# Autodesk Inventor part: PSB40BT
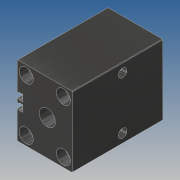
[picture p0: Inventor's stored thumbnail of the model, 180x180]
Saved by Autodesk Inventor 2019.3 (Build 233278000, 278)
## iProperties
Created: 2013-10
Part Number: PSB40BT
Material: Ogólny
Document SubType Name: Modeling
Designer: CADENGINEERING4
Density: 1 g/cm^3
Appearance: Ciemnoszara
Author: CADENGINEERING4
Revision Number: ÈÎºÎ
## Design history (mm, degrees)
feature "ÇÐ³ý-É¨Ãè3"
sketch "Szkic1"
  geometry: C1 r 4.25 at (45.5, -9) reference; C2 r 4.25 at (8.5, -9) reference; C3 r 4.25 at (8.5, -61) reference; C4 r 4.25 at (45.5, -61) reference; 1 further point
sketch "Szkic2"
  geometry: L1 (45.5, -13.25)-(54.5, -13.25) reference; L2 (2.903, -3.2)-(51.311, -3.2); L3 (51.311, -3.2)-(51.311, -13.25); L4 (51.311, -13.25)-(2.903, -13.25); L5 (2.903, -13.25)-(2.903, -3.2); L6 (-0.5, -56.75)-(8.5, -56.75) reference; L7 (2.903, -56.75)-(50.648, -56.75); L8 (50.648, -56.75)-(50.648, -68); L9 (50.648, -68)-(2.903, -68); L10 (2.903, -68)-(2.903, -56.75); 1 further point
  constraints: 16 end point, 4 parallel, 3 point on line, 2 horizontal, 2 perpendicular
extrude "Wyciągnięcie proste1" join sketch "Szkic2" distance "d0" = 20; taper "d1" = 0 deg
sketch "Szkic3"
  geometry: C1 r 1 at (2, 0) reference; 1 further point
hole "Otwór1" sketch "Szkic1" diameter "d2" = 8.376; stored, may be unused: countersink angle "d6" = 90 deg, drill point angle "d8" = 118 deg; dims "d3" = 20, "d4" = 4, "d5" = 2, "d7" = 27.3
extrude "Wyciągnięcie proste2" join sketch "Szkic3" stored distance "d9" = 20; taper "d10" = 0 deg
sketch "Szkic4"
  geometry: L1 (0, 0)-(2.283, 0) reference; L2 (0, 0)-(0, 2) reference; C1 r 8 at (-12, -14) reference; A1 r 20 centre (-12, -14) between (0, 2) and (2.283, 0) reference; 1 further point
  constraints: 1 other
extrude "Wyciągnięcie proste3" join sketch "Szkic4" distance "d11" = 10; taper "d12" = 0 deg
sketch "Szkic5"
  geometry: C1 r 4.1 at (0, 0) reference; 1 further point
hole "Otwór2" sketch "Szkic5" at (0, 0) diameter "d13" = 2; stored, may be unused: countersink angle "d17" = 90 deg, drill point angle "d19" = 118 deg; dims "d14" = 20, "d15" = 4, "d16" = 2, "d18" = 15
node "Bryła1"
node "Pętla rzutowana1"
node "Pętla rzutowana2"
